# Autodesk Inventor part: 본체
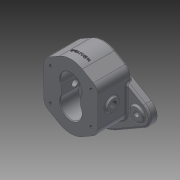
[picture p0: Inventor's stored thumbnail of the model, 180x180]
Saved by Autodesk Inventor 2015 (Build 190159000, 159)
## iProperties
Created: 2025-11
Part Number: 본체
Material: 일반
Document SubType Name: Modeling
Designer: user
Density: 1 g/cm^3
Appearance: 기본값
Author: user
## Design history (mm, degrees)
sketch "스케치1"
  geometry: L1 (74, -17.321)-(26, -45.033); L2 (74, 17.321)-(26, 45.033); L3 (-74, 17.321)-(-26, 45.033); L4 (-26, -45.033)-(-74, -17.321); A1 r 20 centre (64, 0) between (74, -17.321) and (74, 17.321); A2 r 20 centre (-64, 0) between (-74, 17.321) and (-74, -17.321); A3 r 52 centre (0, 0) between (26, 45.033) and (-26, 45.033); 1 further point
  constraints: 8 end point, 8 point on circle, 8 tangent, 3 centre point, 2 horizontal alignment, 1 coincident
  dimensions: "d0" = 40 diameter of A1; "d1" = 40 diameter of A2; "d2" = 128 distance of A2.centre A1.centre; "d3" = 64 distance of point (0, 0) A1.centre; "d4" = 104 diameter of A3
extrude "돌출1" new body sketch "스케치1" distance "d5" = 12; taper "d6" = 0 deg
sketch "스케치2"
  geometry: C1 r 25 at (0, 0); A1 r 52 centre (0, 0) between (26, 45.033) and (-26, 45.033) reference
  constraints: 1 centre point, 1 coincident
  dimensions: "d7" = 50 diameter of C1
extrude "돌출2" join sketch "스케치2" distance "d8" = 4; taper "d9" = 0 deg
sketch "스케치3"
  geometry: C1 r 10 at (-64, 0); C2 r 10 at (64, 0); A1 r 20 centre (-64, 0) between (-74, 17.321) and (-74, -17.321) reference; A2 r 20 centre (64, 0) between (74, -17.321) and (74, 17.321) reference
  constraints: 2 centre point, 2 coincident
  dimensions: "d10" = 20 diameter of C1; "d11" = 20 diameter of C2
extrude "돌출3" join sketch "스케치3" distance "d12" = 3; taper "d13" = 0 deg
sketch "스케치4"
  geometry: C1 r 10 at (0, 0) reference; 1 further point
hole "구멍1" sketch "스케치4" at (0, 0) diameter "d14" = 9; stored, may be unused: countersink angle "d18" = 90 deg, drill point angle "d20" = 118 deg; dims "d15" = 6, "d16" = 4, "d17" = 2, "d19" = 8
sketch "스케치5"
  geometry: C1 r 10 at (0, 0) reference; 1 further point
hole "구멍2" sketch "스케치5" at (0, 0) diameter "d21" = 9; stored, may be unused: countersink angle "d25" = 90 deg, drill point angle "d27" = 118 deg; dims "d22" = 6, "d23" = 4, "d24" = 2, "d26" = 8
sketch "스케치8"
  geometry: L1 (-74, 17.321)-(-26, 45.033) reference; L2 (-37.5, 54.228)-(-19, 64.909); L3 (19, 64.909)-(37.5, 54.228); L4 (19, -32.909)-(37.5, -22.228); L5 (-19, -32.909)-(-37.5, -22.228); L6 (-45, 41.238)-(-45, -9.238); L7 (45, 41.238)-(45, -9.238); A1 r 52 centre (0, 0) between (-26, -45.033) and (26, -45.033) reference; A2 r 52 centre (0, 0) between (26, 45.033) and (-26, 45.033) reference; A3 r 38 centre (0, 32) between (19, 64.909) and (-19, 64.909); A4 r 38 centre (0, 0) between (-19, -32.909) and (19, -32.909); A5 r 15 centre (-30, 41.238) between (-37.5, 54.228) and (-45, 41.238); A6 r 15 centre (30, 41.238) between (45, 41.238) and (37.5, 54.228); A7 r 15 centre (30, -9.238) between (37.5, -22.228) and (45, -9.238); A8 r 15 centre (-30, -9.238) between (-45, -9.238) and (-37.5, -22.228)
  constraints: 12 end point, 12 point on circle, 12 tangent, 6 centre point, 2 equal radius, 2 parallel, 2 vertical, 1 coincident, 1 vertical alignment
  dimensions: "d51" = 76 diameter of A3; "d52" = 76 diameter of A4; "d53" = 32 distance of A3.centre A1.centre; "d54" = 60 deg angle of L5 L2; "d55" = 60 deg angle of L4 L3; "d56" = 90 distance between parallel lines of L6 L7; "d57" = 45 distance from line of A3.centre L7; "d58" = 15 radius of A5; "d59" = 15 radius of A7
extrude "돌출4" join sketch "스케치8" distance "d60" = 48; taper "d62" = 0 deg; dims "d61" = 8, "d63" = 0
sketch "스케치9"
  geometry: C1 r 25 at (0, 0) reference
hole "구멍3" sketch "스케치9" at (0, 0) diameter "d64" = 21; stored, may be unused: countersink angle "d68" = 90 deg, drill point angle "d70" = 118 deg; dims "d65" = 6, "d66" = 30, "d67" = 7.3, "d69" = 8
sketch "스케치10"
  geometry: L1 (16, 23.754)-(16, 8.246); L2 (-16, 23.754)-(-16, 8.246); C1 r 10.5 at (0, 0) reference; A1 r 38 centre (0, 32) between (19, 64.909) and (-19, 64.909) reference; A2 r 38 centre (0, 0) between (-19, -32.909) and (19, -32.909) reference; A3 r 18 centre (0, 0) between (16, 8.246) and (-16, 8.246); A4 r 18 centre (0, 32) between (-16, 23.754) and (16, 23.754)
  constraints: 4 end point, 4 point on circle, 2 centre point, 2 coincident, 2 vertical
  dimensions: "d71" = 36 diameter of A3; "d72" = 36 diameter of A4; "d75" = 32 distance between parallel lines of L1 L2; "d76" = 16 distance from line of A1.centre L2
extrude "돌출5" cut sketch "스케치10" distance "d77" = 31; taper "d78" = 0 deg
sketch "스케치11"
  geometry: A1 r 18 centre (0, 32) between (16, 23.754) and (-16, 23.754) reference
hole "구멍4" sketch "스케치11" at (0, 32) diameter "d79" = 23; stored, may be unused: countersink angle "d83" = 90 deg, drill point angle "d85" = 0 deg; dims "d80" = 6, "d81" = 30, "d82" = 7.3, "d84" = 15
sketch "스케치12"
  geometry: A1 r 18 centre (0, 0) between (-16, 8.246) and (16, 8.246) reference
hole "구멍5" sketch "스케치12" at (0, 0) diameter "d86" = 23; stored, may be unused: countersink angle "d90" = 90 deg, drill point angle "d92" = 0 deg; dims "d87" = 6, "d88" = 30, "d89" = 7.3, "d91" = 15
sketch "스케치13"
  geometry: L1 (43.301, -48)-(-7.174, -48) reference; L2 (59.064, 16)-(9.064, 16) reference; C1 r 10 at (18.064, -25); 1 further point
  constraints: 1 centre point
  dimensions: "d93" = 20 diameter of C1; "d94" = 23 distance from line of L1 C1.centre; "d95" = 16 horizontal distance of C1.centre point (34.064, 0)
extrude "돌출6" join sketch "스케치13" distance "d96" = 3; taper "d97" = 0 deg
sketch "스케치14"
  geometry: C1 r 10 at (0, 0) reference; 1 further point
hole "구멍6" sketch "스케치14" at (0, 0) diameter "d98" = 10.5; stored, may be unused: countersink angle "d104" = 90 deg, drill point angle "d106" = 0 deg; dims "d99" = 11, "d100" = 0.62479, "d101" = 10.589, "d102" = 30, "d103" = 7.3, "d105" = 17.5
sketch "스케치15"
  geometry: C1 r 5.25 at (0, 0) reference; 1 further point
hole "구멍7" sketch "스케치15" at (0, 0) diameter "d107" = 10.5; stored, may be unused: countersink angle "d113" = 90 deg, drill point angle "d115" = 0 deg; dims "d108" = 11, "d109" = 0.62479, "d110" = 10.589, "d111" = 30, "d112" = 7.3, "d114" = 17.5
sketch "스케치16"
  geometry: A1 r 18 centre (0, 32) between (16, 23.754) and (-16, 23.754) reference; A2 r 38 centre (0, 0) between (-19, -32.909) and (19, -32.909) reference; 4 further points
  dimensions: "d116" = 68 distance of point (34, 43) point (-34, 43); "d117" = 34 horizontal distance of A1.centre point (-34, 43); "d118" = 54 distance of point (-34, -11) point (-34, 43); "d119" = 11 vertical distance of A1.centre point (-34, 43); "d120" = 68 distance of point (34, -11) point (-34, -11); "d121" = 34 horizontal distance of A2.centre point (-34, -11); "d122" = 54 distance of point (34, -11) point (34, 43); "d123" = 11 vertical distance of A1.centre point (34, 43)
hole "구멍8" sketch "스케치16" at (-34, 43), (34, 43), (34, -11), (-34, -11) diameter "d124" = 4.917; stored, may be unused: countersink angle "d128" = 90 deg, drill point angle "d130" = 118 deg; dims "d125" = 12, "d126" = 30, "d127" = 7.3, "d129" = 14
fillet "모깎기1" dims "d131" = 0.3
chamfer "모따기1" distance "d132" = 0.7; stored, may be unused: second distance "d133" = 2, angle "d134" = 30 deg
chamfer "모따기2" distance "d135" = 1; stored, may be unused: second distance "d136" = 2, angle "d137" = 30 deg
chamfer "모따기3" distance "d138" = 1; stored, may be unused: second distance "d139" = 2, angle "d140" = 30 deg
node "작업 평면1"
sketch "스케치17"
  geometry: L1 (-19, -48)-(19, -48) reference; L2 (-48, -35)-(-48, -15) reference; 2 further points
  constraints: 1 other
  dimensions: "d141" = 16 distance from line of L1 point (0, -32); "d142" = 48 distance from line of L2 point (0, -32)
feature "엠보싱1" sketch "스케치17" dims "d3" = 64, "d143" = 0.5, "d144" = 0
fillet "모깎기2" dims "d145" = 3
fillet "모깎기3" dims "d146" = 3
node "솔리드1"
mirror "대칭1"
other parameters: "d73" = 32, "d74" = 16
